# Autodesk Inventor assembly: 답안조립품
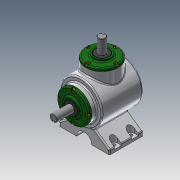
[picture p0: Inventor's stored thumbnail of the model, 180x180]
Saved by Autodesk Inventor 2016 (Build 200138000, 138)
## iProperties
Created: 2017-04
Part Number: 답안조립품
Material: 일반
Document SubType Name: Assembly
Designer: CAMTIC
Author: CAMTIC
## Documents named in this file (14)
- C:\Users\CAMTIC\Desktop\470407V1027\답안조립품.iam
- C:\Users\CAMTIC\Desktop\470407V1027\1-본체.ipt
- C:\Users\CAMTIC\Desktop\470407V1027\메인 베벨기어.ipt
- C:\Users\CAMTIC\Desktop\470407V1027\메인 축.ipt
- 메인 축.ipt
- C:\Users\CAMTIC\Desktop\470407V1027\베어링 6203.ipt
- C:\Users\CAMTIC\Desktop\470407V1027\볼트 M4.ipt
- C:\Users\CAMTIC\Desktop\470407V1027\서브 베벨기어.ipt
- C:\Users\CAMTIC\Desktop\470407V1027\서브 축.ipt
- 서브 축.ipt
- C:\Users\CAMTIC\Desktop\470407V1027\오일실 17 32 8.ipt
- C:\Users\CAMTIC\Desktop\470407V1027\커버.ipt
- C:\Users\CAMTIC\Desktop\470407V1027\키 4x4.ipt
- C:\Users\CAMTIC\Desktop\470407V1027\키 5x5.ipt
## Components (1 placed, 1 different names)
1. 1-본체:1
